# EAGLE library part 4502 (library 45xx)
Stored hex INVERTER/BUFFER
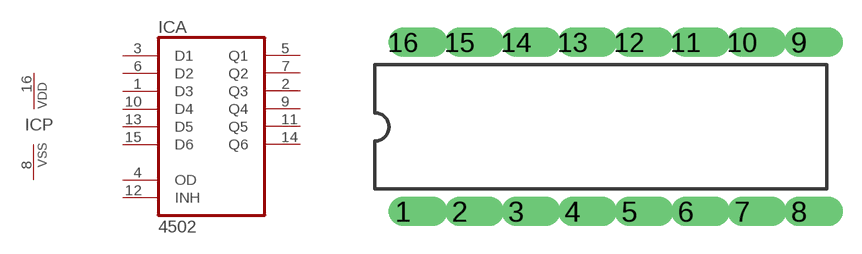
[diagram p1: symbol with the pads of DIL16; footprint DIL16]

Designator prefix IC; gates A=4502 P=PWRN

## 4502N  [DIL16]
1  A:D3  in
2  A:Q3  out
3  A:D1  in
4  A:OD  in
5  A:Q1  out
6  A:D2  in
7  A:Q2  out
8  P:VSS  pwr
9  A:Q4  out
10  A:D4  in
11  A:Q5  out
12  A:INH  in
13  A:D5  in
14  A:Q6  out
15  A:D6  in
16  P:VDD  pwr

## Footprint DIL16 (pad centres in mm)
Dual In Line
drill 0.813 offset: 1 -8.89,-3.81; 2 -6.35,-3.81; 3 -3.81,-3.81; 4 -1.27,-3.81; 5 1.27,-3.81; 6 3.81,-3.81; 7 6.35,-3.81; 8 8.89,-3.81; 9 8.89,3.81; 10 6.35,3.81; 11 3.81,3.81; 12 1.27,3.81; 13 -1.27,3.81; 14 -3.81,3.81; 15 -6.35,3.81; 16 -8.89,3.81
